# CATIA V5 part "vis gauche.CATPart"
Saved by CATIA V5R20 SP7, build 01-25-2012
Part number: vis gauche
Bounding box of the stored display mesh (mm): x 7.86 to 16.96, y 18.5 to 27.5, z 38.221 to 52.221
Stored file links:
  F:\Travaux\Modélisations\CFAO_2011\CFAO_2011_MMS\CFAO_2011_MMS_DONE\CFAO_2011_MMS_jboiteux\Catia\vis gauche.CATPart
  U:\finthinkmotion\stepper.CATProduct
  F:\Travaux\Modélisations\CFAO_2011\CFAO_2011_MMS\CFAO_2011_MMS_DONE\CFAO_2011_MMS_jboiteux\Catia\support pied gauche.CATPart
  F:\Travaux\Modélisations\CFAO_2011\CFAO_2011_MMS\CFAO_2011_MMS_DONE\CFAO_2011_MMS_jboiteux\Catia\Part35.CATPart
  F:\Travaux\Modélisations\CFAO_2011\CFAO_2011_MMS\CFAO_2011_MMS_DONE\CFAO_2011_MMS_jboiteux\Catia\bati.CATPart
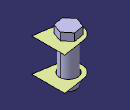
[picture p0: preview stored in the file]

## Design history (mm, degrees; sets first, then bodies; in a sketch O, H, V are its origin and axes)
Parameters
  rayontube = 9 mm {= External.royontubebati}
External parameters (linked from other documents)
  External.royontubebati = 9 mm
Set1
  DatumSurface1: linked copy from another document
  Point1: linked copy from another document
  DatumCurve1: linked copy from another document
  DatumSurface2: linked copy from another document
Body1 (main body)
  Sketch1 on face of DatumSurface1, origin (0, 0, 50.221), H (1, 0, 0), V (0, -1, 0)
    circle A1 centre (11.46, -23) radius 2.15
    point P1 (11.46, -23)
    reference projected point E1 (11.46, -23) from Point1
    radius A1 = 2.15 {= rayontube *43/180}
    coincidence: E1 P1
  Pad1: profile Sketch1, direction (0, 0, -1), up to face of DatumSurface2, offset 3 {= rayontube /3}
  Sketch2 on start face of Pad1, origin (0, 0, 50.221), H (1, 0, 0), V (0, 1, 0)
    point P1 (11.46, 23)
    point P2 (9.6686, 25.1627)
    point P3 (8.6914, 22.53)
    point P4 (10.4828, 20.3673)
    point P5 (13.2514, 20.8373)
    point P6 (14.2286, 23.47)
    point P7 (12.4372, 25.6327)
    point P8 (9.18, 23.8463)
    line L1 (9.6686, 25.1627) -> (8.6914, 22.53)
    line L2 (8.6914, 22.53) -> (10.4828, 20.3673)
    line L3 (10.4828, 20.3673) -> (13.2514, 20.8373)
    line L4 (13.2514, 20.8373) -> (14.2286, 23.47)
    line L5 (14.2286, 23.47) -> (12.4372, 25.6327)
    line L6 (12.4372, 25.6327) -> (9.6686, 25.1627)
    construction line L7 (11.46, 23) -> (9.18, 23.8463)
    construction circle A1 centre (11.46, 23) radius 2.8082
    construction arc A2 centre (14.2286, 23.47) radius 2.8082 from (13.2514, 20.8373) to (12.4372, 25.6327) cw
    construction arc A3 centre (8.6914, 22.53) radius 2.8082 from (10.4828, 20.3673) to (9.6686, 25.1627) ccw
    reference projected point E1 (11.46, 23) from Point1
    reference projected point E2 (11.46, 23) from Point1
    distance E2 L4 = 2.432 {= rayontube *304/1125}
    coincidence: A1 P2, A1 P3, A1 P4, A1 P5, A1 P6, A1 P7, A2 P1, A3 P1, E1 P1
    midpoint: P8 L1
    parallelism: L1 L4
  Pad2: profile Sketch2, direction (0, 0, 1), length 2 {= rayontube /4.5}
